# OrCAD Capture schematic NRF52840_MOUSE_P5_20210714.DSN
size C
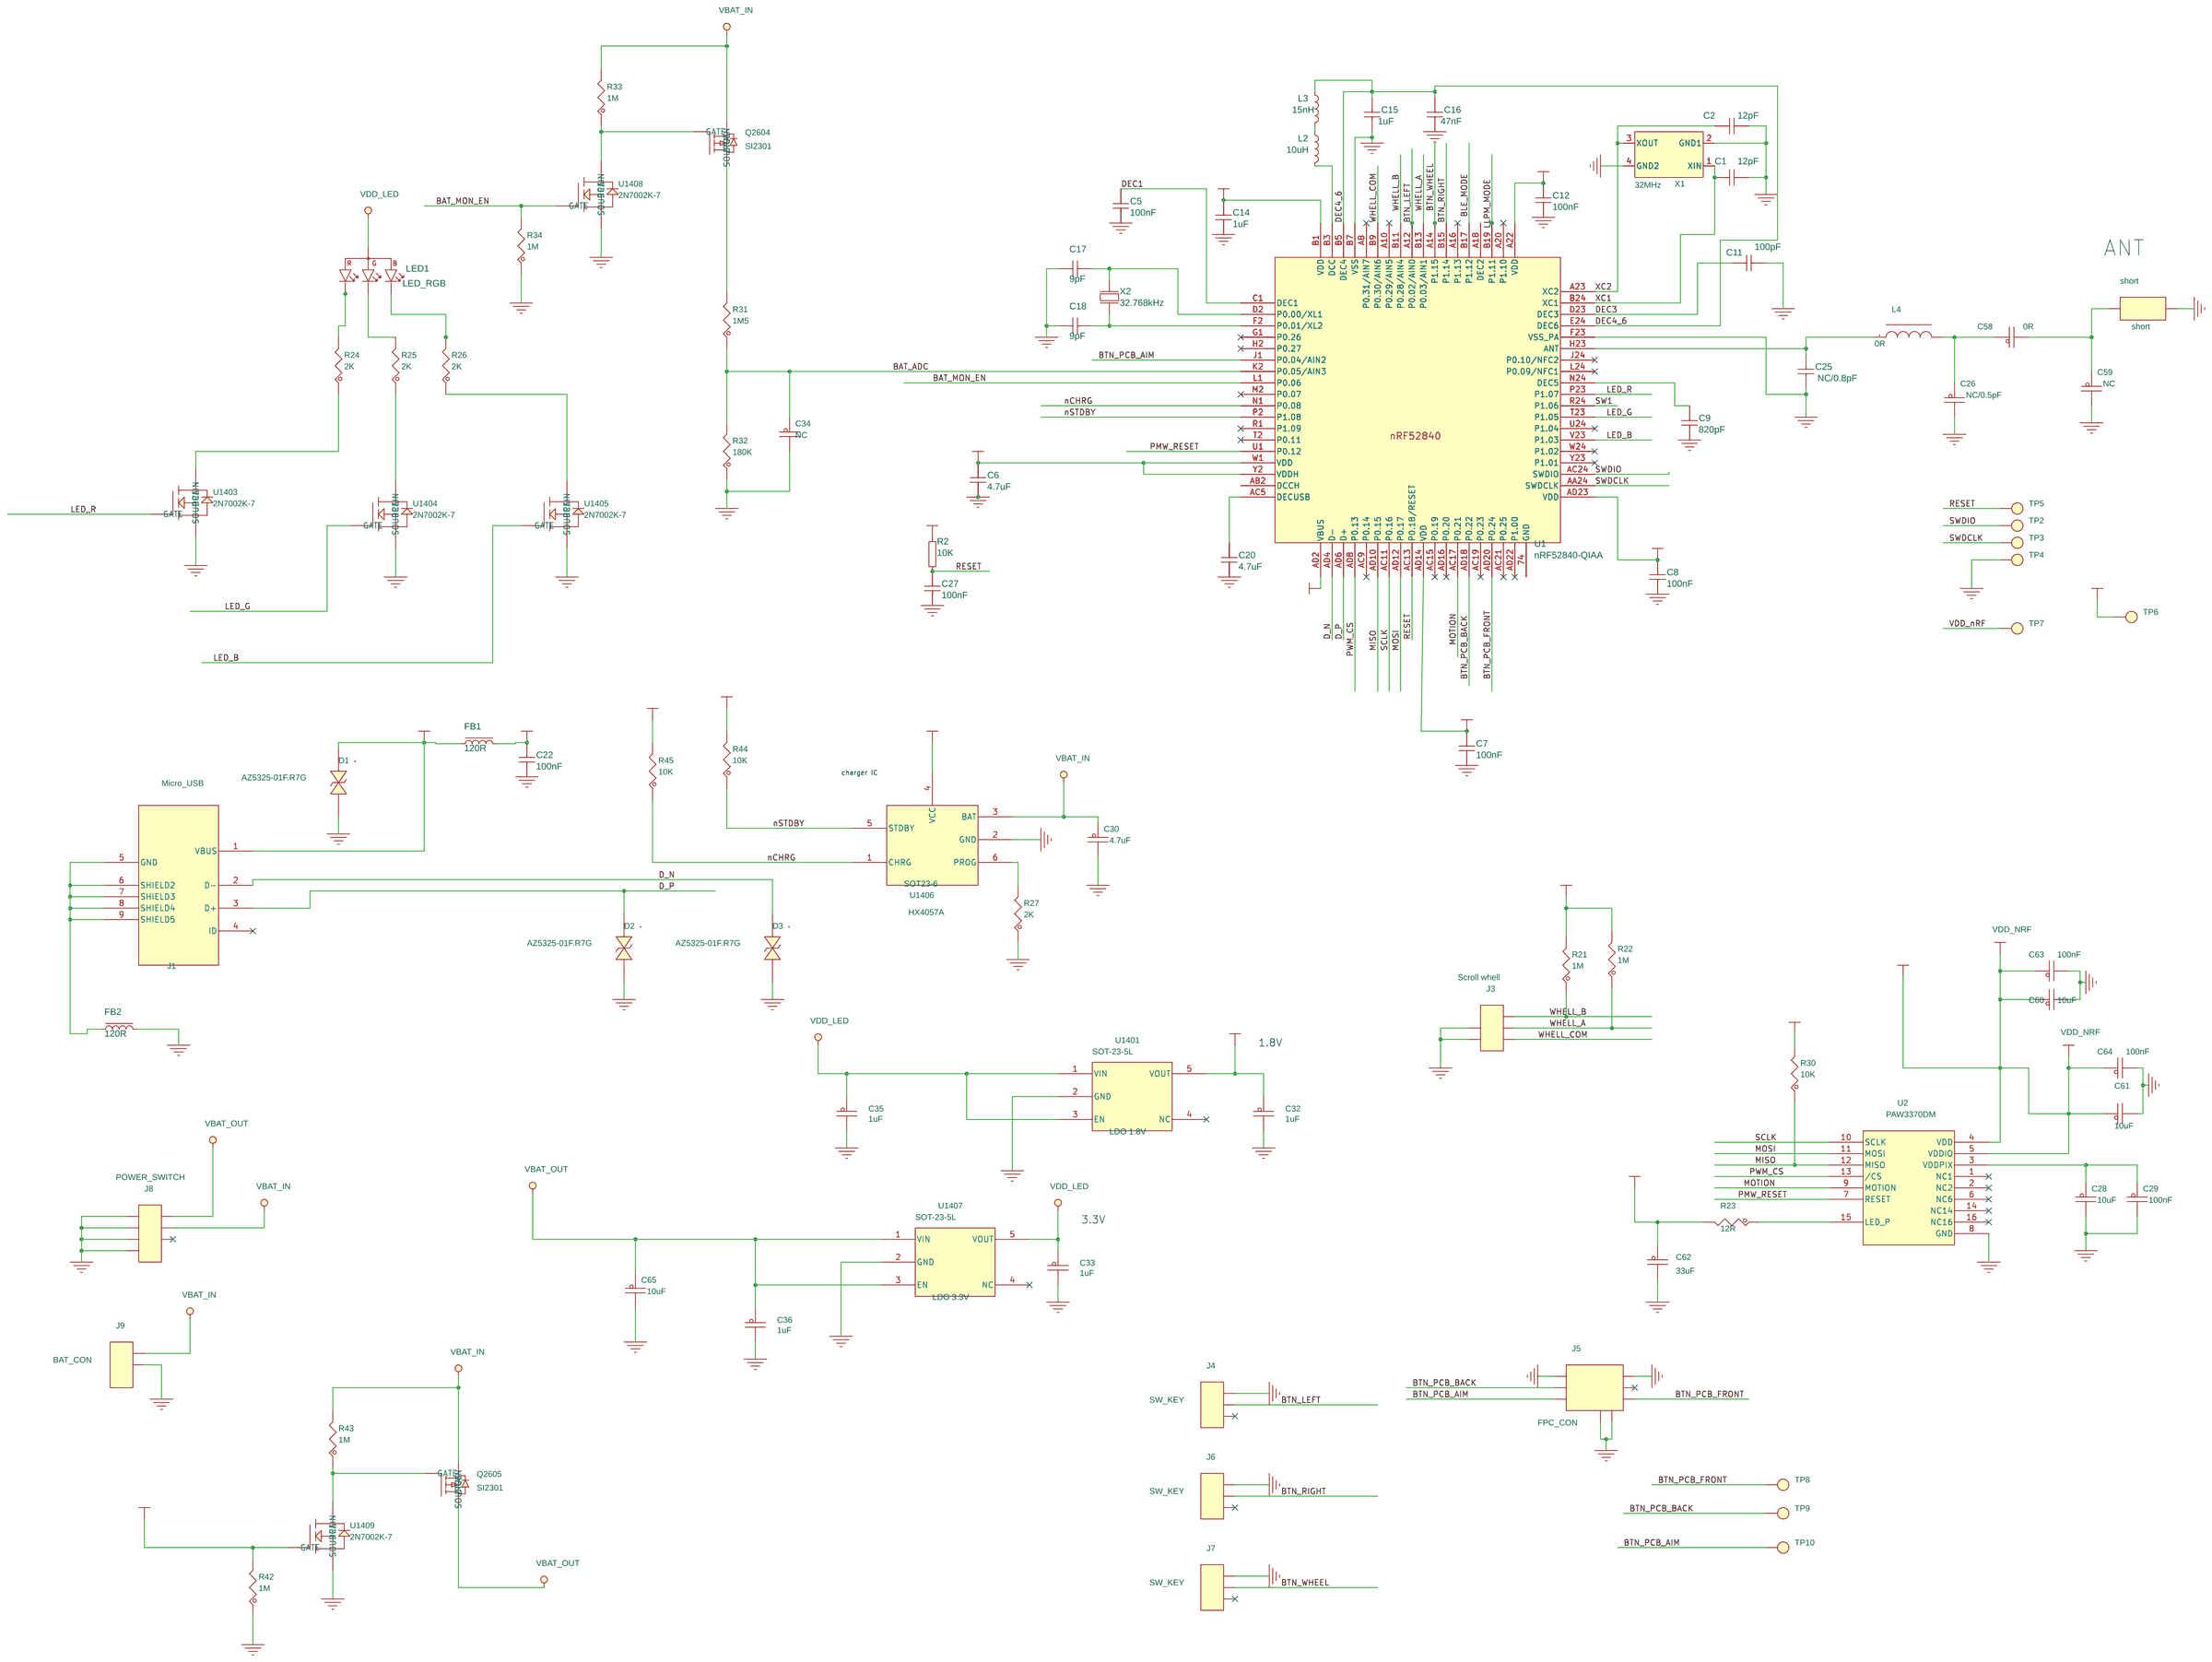
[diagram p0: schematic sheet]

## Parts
C1  12pF  [C0402]
C2  12pF  [C0402]
C5  100nF  [C0402]
C6  4.7uF  [C0402]
C7  100nF  [C0402]
C8  100nF  [C0402]
C9  820pF  [C0402]
C11  100pF  [C0402]
C12  100nF  [C0402]
C14  1uF  [C0402]
C15  1uF  [C0402]
C16  47nF  [C0402]
C17  9pF  [C0402]
C18  9pF  [C0402]
C20  4.7uF  [C0402]
C22  100nF  [C0402]
C25  NC/0.8pF  [C0402]
C26  NC/0.5pF  [C0402]
C27  100nF  [C0402]
C28  10uF  [C0402]
C29  100nF  [C0402]
C30  4.7uF  [C0402]
C32  1uF  [C0402]
C33  1uF  [C0402]
C34  NC  [C0402]
C35  1uF  [C0402]
C36  1uF  [C0402]
C58  0R  [C0402]
C59  NC  [C0402]
C60  10uF  [C1206]
C61  10uF  [C1206]
C62  33uF  [C1206]
C63  100nF  [C0402]
C64  100nF  [C0402]
C65  10uF  [C1206]
D1  AZ5325-01F.R7G  [DFN1006P2E]
D2  AZ5325-01F.R7G  [DFN1006P2E]
D3  AZ5325-01F.R7G  [DFN1006P2E]
FB1  120R  [L0402]
FB2  120R  [L0402]
J1  Micro_USB  [PCBCOMPONENT_1_-_DUPLICATE]
J3  Scroll whell  [ENCODE-DIP-5PIN_-_DUPLICATE]
J4  SW_KEY  [KEYE]
J5  FPC_CON  [FPC_6PINLGUH]
J6  SW_KEY  [KEYE]
J7  SW_KEY  [KEYD1]
J8  POWER_SWITCH  [KEY-20210303]
J9  BAT_CON  [CON5-0303]
L2  10uH  [L0603]
L3  15nH  [L0402]
L4  0R  [L0402]
LED1  LED_RGB  [LED-SMD-1615-RGB_2]
Q2604  SI2301  [SOT_23]
Q2605  SI2301  [SOT_23]
R2  10K  [R0402]
R21  1M  [R0402]
R22  1M  [R0402]
R23  12R  [R0402]
R24  2K  [R0402]
R25  2K  [R0402]
R26  2K  [R0402]
R27  2K  [R0402]
R30  10K  [R0402]
R31  1M5  [R0402]
R32  180K  [R0402]
R33  1M  [R0402]
R34  1M  [R0402]
R42  1M  [R0402]
R43  1M  [R0402]
R44  10K  [R0402]
R45  10K  [R0402]
short  short  [short-1p5x1p8-2PIN]
TP2  TP_0.7  [TP_20]
TP3  TP_0.7  [TP_20]
TP4  TP_0.7  [TP_20]
TP5  TP_0.7  [TP_20]
TP6  TP_0.7  [TP_20]
TP7  TP_0.7  [TP_20]
TP8  TP_0.7  [TP_20]
TP9  TP_0.7  [TP_20]
TP10  TP_0.7  [TP_20]
U1  nRF52840-QIAA  [AQFN50P700X700X85_HS-74N]
U2  PAW3370DM  [PMW3360DM]
U1401  LDO 1.8V  [SOT-23-5L]
U1403  2N7002K-7  [SOT_23]
U1404  2N7002K-7  [SOT_23]
U1405  2N7002K-7  [SOT_23]
U1406  HX4057A  [SOT23-6]
U1407  LDO 3.3V  [SOT-23-5L]
U1408  2N7002K-7  [SOT_23]
U1409  2N7002K-7  [SOT_23]
X1  32MHz  [BT-XTAL_2016]
X2  32.768kHz  [XTAL_2012]

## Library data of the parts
C1 C2 C17 C18 = CAP: 2nd source Supplier: *; 2nd source part number: *; Artikkelnr Noca: N.A.; Artikkelnr Simpro: N.A.; ComponentLink1Description: Datasheet; ComponentLink1URL: *; ComponentLink2Description: Supplier link; ComponentLink2URL: *; Footprint Doc: 0201; HelpURL: *; LatestRevisionDate: 2017-11-09; Manufacturer: *; Manufacturer Part Number: *; Note: 25V; Part Number: C0201-12p; Part number IPS: 00000007848; Pin Count: 2; Published: 2014-11-13; Publisher: Nordic Semiconductor; Supplier: *; Supplier part number: *
C5 C7 C8 C12 C22 C27 = CAP: 2nd source Supplier: *; 2nd source part number: *; Artikkelnr Noca: N.A.; Artikkelnr Simpro: N.A.; ComponentLink1Description: Datasheet; ComponentLink1URL: *; ComponentLink2Description: Supplier link; ComponentLink2URL: *; Footprint Doc: 0201; HelpURL: *; LatestRevisionDate: 2017-11-09; Manufacturer: *; Manufacturer Part Number: *; Note: 16V; Part Number: C0201-100n; Part number IPS: 00000001248; Pin Count: 2; Published: 2014-11-13; Publisher: Nordic Semiconductor; Supplier: *; Supplier part number: *
C6 C20 = CAP: 2nd source Supplier: *; 2nd source part number: *; Artikkelnr Noca: 20069060; Artikkelnr Simpro: N.A.; ComponentLink1Description: Datasheet; ComponentLink1URL: *; ComponentLink2Description: Supplier link; ComponentLink2URL: *; Footprint Doc: 0603; HelpURL: *; LatestRevisionDate: 2009-11-23; Manufacturer: *; Manufacturer Part Number: *; Note: 6.3V; Part Number: C0603-4?; Part number IPS: 00000007783; Pin Count: 2; Published: 2009-05-08; Publisher: Nordic Semiconductor; Supplier: *; Supplier part number: *
C9 = CAP: 2nd source Supplier: *; 2nd source part number: *; Artikkelnr Noca: N.A.; Artikkelnr Simpro: N.A.; ComponentLink1Description: Datasheet; ComponentLink1URL: *; ComponentLink2Description: Supplier link; ComponentLink2URL: *; Footprint Doc: 0201; HelpURL: *; LatestRevisionDate: 2017-11-09; Manufacturer: *; Manufacturer Part Number: *; Note: 25V; Part Number: C0201-820p; Part number IPS: 00000001249; Pin Count: 2; Published: 2014-11-13; Publisher: Nordic Semiconductor; Supplier: *; Supplier part number: *
C11 = CAP: 2nd source Supplier: *; 2nd source part number: *; Artikkelnr Noca: N.A.; Artikkelnr Simpro: N.A.; ComponentLink1Description: Datasheet; ComponentLink1URL: *; ComponentLink2Description: Supplier link; ComponentLink2URL: *; Footprint Doc: 0201; HelpURL: *; LatestRevisionDate: 2017-11-09; Manufacturer: *; Manufacturer Part Number: *; Note: 25V; Part Number: C0201-100p; Part number IPS: 00000007853; Pin Count: 2; Published: 2014-11-13; Publisher: Nordic Semiconductor; Supplier: *; Supplier part number: *
C14 C15 = CAP: 2nd source Supplier: *; 2nd source part number: *; Artikkelnr Noca: 20039335; Artikkelnr Simpro: N.A.; ComponentLink1Description: Datasheet; ComponentLink1URL: *; ComponentLink2Description: Supplier link; ComponentLink2URL: *; Footprint Doc: 0603; HelpURL: *; LatestRevisionDate: 2013-06-05; Manufacturer: *; Manufacturer Part Number: *; Note: 16V; Part Number: C0603-1?; Part number IPS: 00000000616; Pin Count: 2; Published: 2009-05-08; Publisher: Nordic Semiconductor; Supplier: *; Supplier part number: *
C16 = CAP: 2nd source Supplier: *; 2nd source part number: *; Artikkelnr Noca: N.A.; Artikkelnr Simpro: N.A.; ComponentLink1Description: Datasheet; ComponentLink1URL: *; ComponentLink2Description: Supplier link; ComponentLink2URL: *; Footprint Doc: 0201; HelpURL: *; LatestRevisionDate: 2017-11-09; Manufacturer: *; Manufacturer Part Number: *; Note: 10V; Part Number: C0201-47n; Part number IPS: 00000001250; Pin Count: 2; Published: 2014-11-13; Publisher: Nordic Semiconductor; Supplier: *; Supplier part number: *
C25 = CAP: 2nd source Supplier: *; 2nd source part number: *; Artikkelnr Noca: N.A.; Artikkelnr Simpro: N.A.; Assembly: Not mounted; ComponentLink1Description: Datasheet; ComponentLink1URL: *; ComponentLink2Description: Supplier link; ComponentLink2URL: *; Footprint Doc: 0201; HelpURL: *; LatestRevisionDate: 2014-11-13; Manufacturer: *; Manufacturer Part Number: *; Note: Chip Cap; Part Number: C0201-N.C.; Pin Count: 2; Published: 2014-11-13; Publisher: Nordic Semiconductor; Supplier: *; Supplier part number: *
C26 C58 C59 = ceramic_Cap: 厂家: 集合; 高度: 0.6mm; 公司料号: 04-884-104103; 精度: 10%; 料号: 集合料号; 描述: C/C.0.1uF.16V.10%..X7R...SMD 0402....LEAD-FREE(RoHS/HF).; 耐压: 16V
C28-C30 C34 C60-C65 = ceramic_Cap: 厂家: 集合; 高度: 0.6mm; 公司料号: 04-888-106504; 精度: 20%; 料号: 集合料号; 描述: C/C.10uF.6.3V.20%..X5R....SMD 0402....LEAD-FREE(RoHS/HF)..; 耐压: 6.3V
C32 C33 C35 C36 = ceramic_Cap: 厂家: 集合; 高度: 0.6mm; 公司料号: 04-884-100303; 精度: 10%; 料号: 集合料号; 描述: C/C.10pF.50V.10%..X7R....SMD 0402...HF.LEAD-FREE..; 耐压: 50V
D1-D3 = ESD_BI_DFN1006P2E: 厂家: AMAZING; 高度: 0.6mm; 公司料号: 03-013-500115; 描述: ESD PTOR.AZ5325-01F.R7G.......DFN1006P2E......LEAD-FREE(RoHS/HF).AMAZING; 最高工作电压: 7V
FB1 FB2 = IND_F: 2nd source Supplier: *; 2nd source part number: *; Artikkelnr Noca: N.A.; Artikkelnr Simpro: N.A.; ComponentLink1Description: Datasheet; ComponentLink1URL: *; ComponentLink2Description: Supplier link; Footprint Doc: 0402; HelpURL: http://ds.yuden.co.jp/TYCOMPAS/ut/detail.do?productNo=BKP0603HS121-T&fileName=BKP0603HS121-T_SS&mode=specSheetDownload; LatestRevisionDate: 2016-08-23; Manufacturer: Taiyo Yuden; Manufacturer Part Number: BKP0603HS121-T; Note: Chip EMIFIL Inductor Type Chip Ferrite Bead; Part Number: FB0201-120R@100M-850mA; Part number IPS: 00000001252; Pin Count: 2; Published: 2016-08-23; Publisher: Nordic Semiconductor; Supplier: Digi-Key; Supplier part number: 587-3286-1-ND
J1 = UN1159C-N1211-7H_1: 厂家: FOXCONN; 高度: 2.5mm; 公司料号: 10-084-005083; 料号: UN1159C-N1211-7H; 描述: CONN.MICRO USB B-TYPE..5P 90D SMD......G/F+Pd/Ni 30u..3.2A...BLACK.UN1159C-N1211-7H....LEAD-FREE(RoHS/HF).FOXCONN
J3 = Header-2_0: 厂家: L&S; 高度: 11.6; 公司料号: 10-341-003826; 料号: BLACK.1100312100; 描述: HEADER...3*1 180D...........BLACK.1100312100....LEAD-FREE(RoHS).L&S
J4 J6 J7 = Header-2_3: 厂家: L&S; 高度: 11.6; 公司料号: 10-341-003826; 料号: BLACK.1100312100; 描述: HEADER...3*1 180D...........BLACK.1100312100....LEAD-FREE(RoHS).L&S
J5 = Header-2_7: 厂家: L&S; 高度: 11.6; 公司料号: 10-341-003826; 料号: BLACK.1100312100; 描述: HEADER...3*1 180D...........BLACK.1100312100....LEAD-FREE(RoHS).L&S
J8 = Header-2_5: 厂家: L&S; 高度: 11.6; 公司料号: 10-341-003826; 料号: BLACK.1100312100; 描述: HEADER...3*1 180D...........BLACK.1100312100....LEAD-FREE(RoHS).L&S
J9 = Header-2_6: 厂家: L&S; 高度: 11.6; 公司料号: 10-341-003826; 料号: BLACK.1100312100; 描述: HEADER...3*1 180D...........BLACK.1100312100....LEAD-FREE(RoHS).L&S
L2 = IND: 2nd source Supplier: Farnell; 2nd source part number: 178-6105; Artikkelnr Noca: 33029314; Artikkelnr Simpro: N.A.; ComponentLink1Description: Datasheet; ComponentLink1URL: *; ComponentLink2Description: Supplier link; Footprint Doc: 0603; HelpURL: http://www.yuden.co.jp/ut/product/pdf/elb2_e.pdf; LatestRevisionDate: 2012-09-19; Manufacturer: Taiyo Yuden; Manufacturer Part Number: LBMF1608T100K; Note: LBMF1608T100K 10µH 80mA 0603; Part Number: L0603-10?; Part number IPS: 00000007794; Pin Count: 2; Published: 2010-02-24; Publisher: Nordic Semiconductor; Supplier: Digi-Key; Supplier part number: 587-1714-1-ND
L3 = IND: 2nd source Supplier: Farnell; 2nd source part number: 658-1328; Artikkelnr Noca: 33029323; Artikkelnr Simpro: N.A.; ComponentLink1Description: Datasheet; ComponentLink1URL: *; ComponentLink2Description: Supplier link; Footprint Doc: 0402; HelpURL: http://www.yuden.co.jp/productdata/catalog/en/mlci04_e.pdf; LatestRevisionDate: 2012-09-19; Manufacturer: Taiyo Yuden; Manufacturer Part Number: HK100515NJ-T; Note: High frequency chip inductor ?0%; Part Number: L0402-15n; Part number IPS: 00000001262; Pin Count: 2; Published: 2010-07-12; Publisher: Nordic Semiconductor; Supplier: Digi-Key; Supplier part number: 587-1521-1-ND
L4 = Inductors: 饱和电流: 2.3A; 厂家: TAI-TECH; 感值: 2.2uH; 高度: 1.2mm; 公司料号: 08-413-225996; 精度: 20%; 料号: DFP252012TF-2R2M; 描述: POWER IND.2.2uH.20%.2.3A.0.102 OHM....SMD.2.5*2*1.2mm.DFP252012TF-2R2M....LEAD-FREE(RoHS/HF).TAI-TECH; 直流电阻: 102m
LED1 = LED_RGB_1
Q2604 Q2605 = P-MOSFET_SOT_23: 厂家: WILLSEMI; 高度: 1.3mm; 公司料号: 03-050-502672; 料号: WPM2026-3/TR; 描述: MOSFET P-CH.WPM2026-3/TR..Vds=-20V,Vgs=-12V.Id=-3.2A.Rds(on)=0.056 OHM.SOT-23.....LEAD-FREE(RoHS/HF).WILLSEMI
R2 = RES_1: 2nd source Supplier: *; 2nd source part number: *; Artikkelnr Noca: N.A.; Artikkelnr Simpro: N.A.; ComponentLink1Description: Datasheet; ComponentLink1URL: *; ComponentLink2Description: Supplier link; ComponentLink2URL: *; Footprint Doc: 0201; HelpURL: *; LatestRevisionDate: 2014-11-13; Manufacturer: *; Manufacturer Part Number: *; Note: Chip Res 1%; Part Number: R0201-10k; Part number IPS: 00000001255; Pin Count: 2; Published: 2014-11-13; Publisher: Nordic Semiconductor; Supplier: *; Supplier part number: *; Value Ohm: 10000
R21-R27 R30-R34 R42-R45 = ceramic_Res: 厂家: 集合; 高度: 0.6mm; 功率: 1/16W; 公司料号: 05-152-000100; 精度: 5%; 料号: 集合料号; 描述: RES.0 OHM.1/16W.5%..SMD 0402......LEAD-FREE(RoHS/HF)..
short = TP_0: Test Point 0.7mm; Created by: CZD; Part Type: TP; Priority: A; RK PN: TESTPOINT_0R7
TP2-TP10 = TP: Test Point 0.7mm; Created by: CZD; Priority: A; RK PN: TESTPOINT_0R7
U1 = nRF52840_QIAA: Artikkelnr Noca: N.A.; ComponentLink1Description: Datasheet; ComponentLink1URL: *; ComponentLink2Description: Supplier link; ComponentLink2URL: *; Footprint Doc: AQFN-73; HelpURL: *; LatestRevisionDate: 2018-12-04; Manufacturer: Nordic Semiconductor; Manufacturer Part Number: nRF52840-QIAAD0; Note: *; Part Number: nRF52840-QIAAD0; Part number IPS: N.A.; Pin Count: 73; Published: 2018-12-04; Publisher: Nordic Semiconductor; Supplier 1: Nordic Semiconductor; Supplier 2: *; Supplier Part Number 1: nRF52840-QIAAD0; Supplier Part Number 2: *
U2 = DCDC_SY8254RAC_0: 厂家: SILERGY; 高度: 0.55mm; 公司料号: 02-437-254860; 料号: SY8254RAC; 描述: IC CONV.SY8254RAC..QFN 20P...4A....LEAD-FREE(RoHS/HF).SILERGY; 最大输出电流: 4A
U1401 U1407 = DC_DC_SOT_23_2: 厂家: SILERGY; 高度: 1.3mm; 公司料号: 02-431-089860; 料号: SY8089A1AAC; 描述: IC CONV.SY8089A1AAC..SOT-23-5.2A.....HF.LEAD-FREE.SILERGY; 最大输出电流: 2A
U1403-U1405 U1408 U1409 = N-MOSFET_SOT_23: 厂家: ROHM; 高度: 1.3mm; 公司料号: 03-054-000210; 料号: RUM002N02GT2L; 描述: MOSFET N-CH.RUM002N02GT2L..Vds=20V,Vgs=8V.Id=200mA.Rds=1.2 OHM.VMT3.....LEAD-FREE(RoHS/HF).ROHM
U1406 = DC_DC_SOT_23_4: 厂家: SILERGY; 高度: 1.3mm; 公司料号: 02-431-089860; 料号: SY8089A1AAC; 描述: IC CONV.SY8089A1AAC..SOT-23-5.2A.....HF.LEAD-FREE.SILERGY; 最大输出电流: 2A
X1 = CRYSTAL_3225: 厂家: FUJICOM; 高度: 0.9mm; 公司料号: 07-178-240097; 料号: FSX3M 24.000000M12FEJ; 描述: XTAL.24MHz.10ppm.12pF..SMD 4P.3.2*2.5*0.9mm..FSX3M 24.000000M12FEJ....LEAD-FREE(RoHS/HF).FUJICOM
X2 = XTAL_2-pin: 2nd source Supplier: *; 2nd source part number: *; Artikkelnr Noca: N.A.; Artikkelnr Simpro: N.A.; ComponentLink1Description: Datasheet; ComponentLink1URL: *; ComponentLink2Description: Supplier link; ComponentLink2URL: *; HelpURL: http://www.sii.co.jp/en/quartz/files/2013/03/file_PRODUCT_MASTER_50811_GRAPHIC03.pdf; LatestRevisionDate: 2017-11-09; Manufacturer: Seiko; Manufacturer Part Number: SC20S-9.0PF20PPM; Note: XTAL SMD 32.768kHz; Part Number: XTAL_SMD2012_32.768kHz_9pF_Seiko; Part number IPS: 80000001425; Pin Count: 2; Published: 2015-10-15; Publisher: Nordic Semiconductor; Supplier: *; Supplier part number: *

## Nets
GND: C1.2 C2.2 C5.2 C6.2 C7.2 C8.2 C9.2 C11.2 C12.2 C14.2 C15.1 C16.2 C17.2 C18.2 C20.2 C22.1 C25.2 C26.2 C27.1 C28.2 C29.2 C30.2 C32.2 C33.2 C34.2 C35.2 C36.2 C59.2 C60.2 C61.2 C62.2 C63.2 C64.2 C65.2 D1.2 D2.2 D3.2 FB2.2 J3.4 J3.5 J4.2 J5.1 J5.2 J5.7 J5.8 J6.2 J7.2 J8.4 J8.5 J8.6 J8.7 J9.2 R27.1 R32.1 R34.1 R42.1 short.1 TP4.1 U1.74(GND) U1.B7(VSS) U1.F23(VSS_PA) U2.8(GND) U1401.2(GND) U1403.2(SOURCE) U1404.2(SOURCE) U1405.2(SOURCE) U1406.2(GND) U1407.2(GND) U1408.2(SOURCE) U1409.2(SOURCE) X1.2(GND1) X1.4(GND2)
VBAT_IN: C30.1 J8.2 J9.1 Q2604.2(SOURCE) Q2605.2(SOURCE) R33.2 R43.2 U1406.3(BAT)
VBAT_OUT: C36.1 C65.1 J8.1 Q2605.3(DRAIN) U1407.1(VIN) U1407.3(EN)
VBUS: D1.1 FB1.1 J1.1(VBUS)
VBUS_nRF: C22.2 FB1.2 R42.2 TP6.1 U1.AD2(VBUS) U1406.4(VCC) U1409.1(GATE)
VDD: C6.1 C7.1 C8.1 C12.1 C14.1 C32.1 C60.1 C61.1 C62.1 C63.1 C64.1 R2.2 R21.2 R22.2 R23.2 R30.2 R44.2 R45.2 TP7.1 U1.A22(VDD) U1.AD14(VDD) U1.AD23(VDD) U1.B1(VDD) U1.W1(VDD) U1.Y2(VDDH) U2.4(VDD) U2.5(VDDIO) U1401.5(VOUT)
VDD_LED: C33.1 C35.1 LED1.4(A) U1401.1(VIN) U1401.3(EN) U1407.5(VOUT)
BAT_ADC: C34.1 R31.1 R32.2 U1.K2(P0.05/AIN3)
BAT_MON_EN: R34.2 U1.L1(P0.06) U1408.1(GATE)
BLE_MODE: U1.B17(P1.12)
BTN_LEFT: J4.1 U1.A12(P0.02/AIN0)
BTN_PCB_AIM: J5.6 TP10.1 U1.J1(P0.04/AIN2)
BTN_PCB_BACK: J5.4 TP9.1 U1.AD18(P0.22)
BTN_PCB_FRONT: J5.5 TP8.1 U1.AD20(P0.24)
BTN_RIGHT: J6.1 U1.B15(P1.14)
BTN_WHEEL: J7.1 U1.A14(P1.15)
D_N: D3.1 J1.2(D-) U1.AD4(D-)
D_P: D2.1 J1.3(D+) U1.AD6(D+)
DCCH: U1.AB2(DCCH)
DEC1: C5.1 U1.C1(DEC1)
DEC2: U1.A18(DEC2)
DEC3: C11.1 U1.D23(DEC3)
DEC4_6: C15.2 C16.1 L3.1 U1.B5(DEC4) U1.E24(DEC6)
LED_B: U1.V23(P1.03) U1405.1(GATE)
LED_G: U1.T23(P1.05) U1404.1(GATE)
LED_R: U1.P23(P1.07) U1403.1(GATE)
LLPM_MODE: U1.B19(P1.11)
MISO: R30.1 U1.AD10(P0.15) U2.12(MISO)
MOSI: U1.AD12(P0.17) U2.11(MOSI)
MOTION: U1.AC17(P0.21) U2.9(MOTION)
nCHRG: R45.1 U1.N1(P0.08) U1406.1(CHRG)
nSTDBY: R44.1 U1.P2(P1.08) U1406.5(STDBY)
PMW_RESET: U1.U1(P0.12) U2.7(RESET)
PWM_CS: U1.AD8(P0.13) U2.13(/CS)
RESET: C27.2 R2.1 TP5.1 U1.AC13(P0.18/RESET)
SCLK: U1.AC11(P0.16) U2.10(SCLK)
SW1: U1.R24(P1.06)
SWDCLK: TP3.1 U1.AA24(SWDCLK)
SWDIO: TP2.1 U1.AC24(SWDIO)
WHELL_A: J3.2 R22.1 U1.B13(P0.03/AIN1)
WHELL_B: J3.1 R21.1 U1.B11(P0.28/AIN4)
WHELL_COM: J3.3 U1.B9(P0.30/AIN6)
XC1: C1.1 U1.B24(XC1) X1.1(XIN)
XC2: C2.1 U1.A23(XC2) X1.3(XOUT)
N00013: C9.1 U1.N24(DEC5)
N00015: C20.1 U1.AC5(DECUSB)
N00024: L2.1 L3.2
N00025: L2.2 U1.B3(DCC)
N00047: C17.1 U1.D2(P0.00/XL1) X2.1(inp)
N00048: C18.1 U1.F2(P0.01/XL2) X2.2(out)
N00074: C25.1 L4.1 U1.H23(ANT)
N00235: FB2.1 J1.5(GND) J1.6(SHIELD2) J1.7(SHIELD3) J1.8(SHIELD4) J1.9(SHIELD5)
N372358: R23.1 U2.15(LED_P)
N372603: C28.1 C29.1 U2.3(VDDPIX)
N379055: LED1.1(C_RED) R24.2
N379073: LED1.2(C_GREEN) R25.2
N379080: LED1.3(C_BLUE) R26.2
N379134: R24.1 U1403.3(DRAIN)
N379451: R25.1 U1404.3(DRAIN)
N379621: R26.1 U1405.3(DRAIN)
N384910: R27.2 U1406.6(PROG)
N404039: Q2604.1(GATE) R33.1 U1408.3(DRAIN)
N404214: Q2604.3(DRAIN) R31.2
N445725: Q2605.1(GATE) R43.1 U1409.3(DRAIN)
N454705: C26.1 C58.1 L4.2
N455919: C58.2 C59.1 short.2

Not connected (* = marked no-connect by the designer): J1 4(ID)*; J4 3*; J5 3*; J6 3*; J7 3*; J8 3*; U1 A8(P0.31/AIN7)* A10(P0.29/AIN5)* A16(P1.13)* A20(P1.10)* AC9(P0.14)* AC15(P0.19)* AC19(P0.23)* AC21(P0.25)* AD16(P0.20)* AD22(P1.00)* G1(P0.26)* H2(P0.27)* J24(P0.10/NFC2)* L24(P0.09/NFC1)* M2(P0.07)* R1(P1.09)* T2(P0.11)* U24(P1.04)* W24(P1.02)* Y23(P1.01)*; U2 1(NC1)* 2(NC2)* 6(NC6)* 14(NC14)* 16(NC16)*; U1401 4(NC)*; U1407 4(NC)*

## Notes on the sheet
- ANT
- charger IC
- 1.8V
- 3.3V
